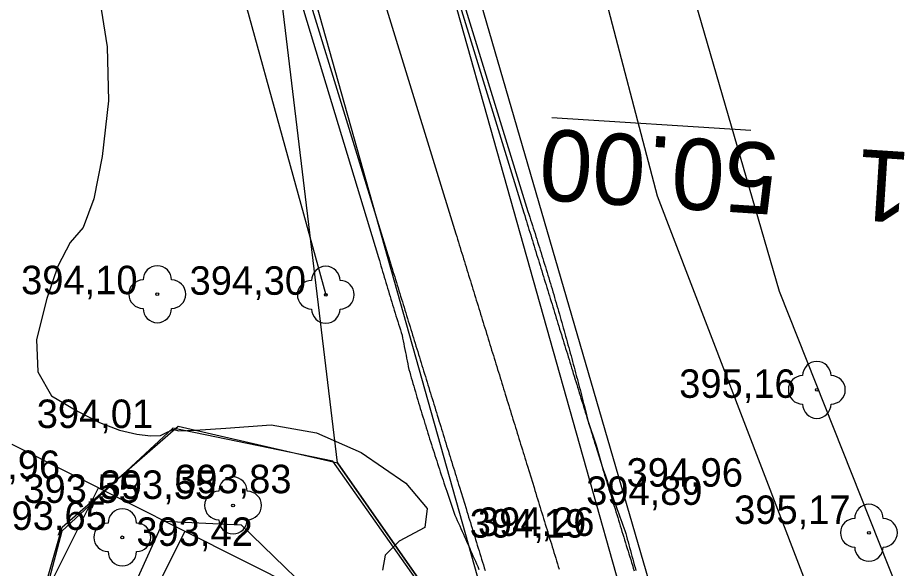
# Model space of a CAD drawing. Extents: x -574342 to -507939, y -1144044 to -1123894.
# Drawn here: x -508498.24 to -508467.17, y -1143116.72 to -1143097.38 of the extents above; entities that cross this region are included whole.
import ezdxf

# ---------------------------------------------------------------- set-up
doc = ezdxf.new("R2010")
doc.units = 0
for name, color, linetype in [('01_PARCELY_NAVRH_PC', 7, 'Continuous'), ('01_PARCELY_NAVRH_VHO', 7, 'Continuous'), ('01_PARCELY_NAVRH_ŽP', 7, 'Continuous'), ('1000', 7, 'Continuous'), ('19', 7, 'Continuous'), ('21', 7, 'Continuous'), ('37', 7, 'Continuous'), ('51', 7, 'Continuous'), ('54', 7, 'Continuous'), ('55', 7, 'Continuous'), ('6', 7, 'Continuous'), ('60', 7, 'Continuous'), ('Level 255', 7, 'Continuous'), ('SO 101_popis oblouku', 7, 'Continuous'), ('VRST VEDL', 7, 'Continuous')]:
    doc.layers.add(name, color=color, linetype=linetype)

msp = doc.modelspace()

# ---------------------------------------------------------------- linework, layer by layer
at = {"layer": '01_PARCELY_NAVRH_PC'}
msp.add_lwpolyline([(-508499.26, -1143041.98), (-508491.15, -1143065.29), (-508474.05, -1143124.14), (-508479.46, -1143126.74), (-508483.82, -1143117.57), (-508487.01, -1143113.01), (-508489.36, -1143093.44), (-508498.08, -1143065.7), (-508506.03, -1143042.25)], close=True, dxfattribs=at)
at = {"layer": '01_PARCELY_NAVRH_VHO'}
msp.add_lwpolyline([(-508498.01, -1143119.91), (-508496.68, -1143115.27), (-508492.61, -1143111.73), (-508487.01, -1143113.01), (-508483.82, -1143117.57)], dxfattribs=at)
at = {"layer": '01_PARCELY_NAVRH_ŽP'}
msp.add_lwpolyline([(-508540.355, -1142847.7), (-508503.94, -1143018.7), (-508499.26, -1143041.98), (-508491.15, -1143065.29), (-508474.05, -1143124.14), (-508467.92, -1143139.18), (-508459.97, -1143152.33), (-508456.09, -1143158.71), (-508451.57, -1143168.14), (-508437.66, -1143207.58), (-508425.52, -1143241.92), (-508422.7, -1143249.88), (-508420.04, -1143252.1), (-508417.38, -1143252.95), (-508415.56, -1143252.78), (-508448.24, -1143160.16), (-508453.75, -1143145.01), (-508465.11, -1143123.03), (-508471.48, -1143106.99), (-508484.55, -1143061.98), (-508495.62, -1143031.06), (-508523.23, -1142904.28), (-508534.61, -1142847.7)], dxfattribs=at)
for points in [[(-508415.56, -1143252.78), (-508448.24, -1143160.16), (-508453.75, -1143145.01), (-508465.11, -1143123.03), (-508471.48, -1143106.99), (-508484.55, -1143061.98), (-508446.15, -1143057.71)], [(-508523.79, -1143164.91), (-508521.99, -1143159.7), (-508510.09, -1143151.01), (-508503.75, -1143144.67), (-508499.11, -1143135.6), (-508498.41, -1143129.24), (-508498.01, -1143119.91), (-508496.68, -1143115.27), (-508492.61, -1143111.73), (-508487.01, -1143113.01), (-508489.36, -1143093.44), (-508492.06, -1143088.51), (-508497.53, -1143088.05), (-508501.63, -1143092.13), (-508501.93, -1143102.81), (-508505.79, -1143121.37), (-508513.07, -1143136.47), (-508529.25, -1143158.67), (-508535.17, -1143170.73), (-508530.07, -1143174.68), (-508525.32, -1143175.64)]]:
    msp.add_lwpolyline(points, close=True, dxfattribs=at)
at = {"layer": '1000'}
for points in [[(-508486.074, -1143086.015), (-508480.463, -1143104.231), (-508480.433, -1143104.329), (-508480.403, -1143104.426), (-508480.373, -1143104.523), (-508480.343, -1143104.62), (-508480.313, -1143104.718), (-508480.283, -1143104.815), (-508480.253, -1143104.912), (-508480.223, -1143105.009), (-508480.193, -1143105.106), (-508480.163, -1143105.204), (-508480.133, -1143105.301), (-508480.103, -1143105.398), (-508480.073, -1143105.495), (-508480.043, -1143105.593), (-508480.013, -1143105.69), (-508479.983, -1143105.787), (-508479.953, -1143105.884), (-508479.924, -1143105.981), (-508479.894, -1143106.079), (-508479.864, -1143106.176), (-508479.834, -1143106.273), (-508479.804, -1143106.37), (-508479.774, -1143106.468), (-508479.744, -1143106.565), (-508479.714, -1143106.662), (-508479.684, -1143106.759), (-508479.654, -1143106.856), (-508479.624, -1143106.954), (-508479.594, -1143107.051), (-508479.564, -1143107.148), (-508479.534, -1143107.245), (-508479.504, -1143107.343), (-508479.474, -1143107.44), (-508479.444, -1143107.537), (-508479.414, -1143107.634), (-508479.384, -1143107.731), (-508479.355, -1143107.829), (-508479.325, -1143107.926), (-508479.295, -1143108.023), (-508479.265, -1143108.12), (-508479.235, -1143108.218), (-508479.205, -1143108.315), (-508479.175, -1143108.412), (-508479.145, -1143108.509), (-508479.115, -1143108.606), (-508479.085, -1143108.704), (-508479.055, -1143108.801), (-508479.025, -1143108.898), (-508478.995, -1143108.995), (-508478.965, -1143109.093), (-508478.935, -1143109.19), (-508478.905, -1143109.287), (-508478.875, -1143109.384), (-508478.845, -1143109.481), (-508478.815, -1143109.579), (-508478.786, -1143109.676), (-508478.756, -1143109.773), (-508478.726, -1143109.87), (-508478.696, -1143109.968), (-508478.669, -1143110.055), (-508478.666, -1143110.065), (-508478.636, -1143110.162), (-508478.606, -1143110.259), (-508478.576, -1143110.357), (-508478.546, -1143110.454), (-508478.516, -1143110.551), (-508478.486, -1143110.648), (-508478.456, -1143110.745), (-508478.426, -1143110.843), (-508478.396, -1143110.94), (-508478.366, -1143111.037), (-508478.336, -1143111.134), (-508478.306, -1143111.232), (-508478.276, -1143111.329), (-508478.246, -1143111.426), (-508478.216, -1143111.523), (-508478.187, -1143111.62), (-508478.157, -1143111.718), (-508478.127, -1143111.815), (-508478.097, -1143111.912), (-508478.067, -1143112.009), (-508478.037, -1143112.107), (-508478.007, -1143112.204), (-508477.977, -1143112.301), (-508477.947, -1143112.398), (-508477.716, -1143113.147), (-508477.686, -1143113.246), (-508477.655, -1143113.345), (-508477.625, -1143113.444), (-508477.594, -1143113.543), (-508477.564, -1143113.642), (-508477.533, -1143113.741), (-508477.503, -1143113.84), (-508477.472, -1143113.939), (-508477.442, -1143114.038), (-508477.411, -1143114.137), (-508477.381, -1143114.236), (-508477.35, -1143114.335), (-508477.32, -1143114.434), (-508477.289, -1143114.533), (-508477.259, -1143114.632), (-508477.228, -1143114.731), (-508477.198, -1143114.83), (-508477.167, -1143114.929), (-508477.137, -1143115.028), (-508477.106, -1143115.127), (-508477.076, -1143115.226), (-508477.046, -1143115.325), (-508477.015, -1143115.424), (-508476.985, -1143115.523), (-508476.954, -1143115.622), (-508476.924, -1143115.721), (-508476.893, -1143115.82), (-508476.863, -1143115.918), (-508476.832, -1143116.017), (-508476.802, -1143116.116), (-508476.771, -1143116.215), (-508476.741, -1143116.314), (-508476.71, -1143116.413), (-508476.68, -1143116.512), (-508476.649, -1143116.611), (-508476.619, -1143116.71), (-508476.588, -1143116.809)], [(-508485.925, -1143085.969), (-508480.32, -1143104.188), (-508480.289, -1143104.284), (-508480.257, -1143104.381), (-508480.226, -1143104.478), (-508480.195, -1143104.575), (-508480.164, -1143104.671), (-508480.132, -1143104.768), (-508480.101, -1143104.865), (-508480.071, -1143104.962), (-508480.04, -1143105.059), (-508480.009, -1143105.156), (-508479.978, -1143105.253), (-508479.948, -1143105.35), (-508479.918, -1143105.447), (-508479.887, -1143105.544), (-508479.857, -1143105.642), (-508479.827, -1143105.739), (-508479.797, -1143105.836), (-508479.767, -1143105.933), (-508479.737, -1143106.03), (-508479.707, -1143106.128), (-508479.678, -1143106.225), (-508479.648, -1143106.322), (-508479.619, -1143106.42), (-508479.589, -1143106.517), (-508479.56, -1143106.615), (-508479.531, -1143106.712), (-508479.502, -1143106.809), (-508479.473, -1143106.907), (-508479.444, -1143107.005), (-508479.415, -1143107.102), (-508479.386, -1143107.2), (-508479.357, -1143107.297), (-508479.329, -1143107.395), (-508479.3, -1143107.493), (-508479.272, -1143107.59), (-508479.244, -1143107.688), (-508479.216, -1143107.786), (-508479.188, -1143107.884), (-508479.16, -1143107.982), (-508479.132, -1143108.079), (-508479.104, -1143108.177), (-508479.076, -1143108.275), (-508479.049, -1143108.373), (-508479.021, -1143108.471), (-508478.994, -1143108.569), (-508478.966, -1143108.667), (-508478.939, -1143108.765), (-508478.912, -1143108.863), (-508478.885, -1143108.961), (-508478.858, -1143109.06), (-508478.831, -1143109.158), (-508478.804, -1143109.256), (-508478.778, -1143109.354), (-508478.751, -1143109.452), (-508478.725, -1143109.551), (-508478.698, -1143109.649), (-508478.672, -1143109.747), (-508478.646, -1143109.846), (-508478.62, -1143109.944), (-508478.596, -1143110.033), (-508478.593, -1143110.043), (-508478.568, -1143110.141), (-508478.542, -1143110.24), (-508478.516, -1143110.338), (-508478.49, -1143110.437), (-508478.465, -1143110.535), (-508478.439, -1143110.634), (-508478.414, -1143110.732), (-508478.389, -1143110.831), (-508478.363, -1143110.93), (-508478.338, -1143111.029), (-508478.313, -1143111.127), (-508478.289, -1143111.226), (-508478.264, -1143111.325), (-508478.239, -1143111.424), (-508478.214, -1143111.523), (-508477.926, -1143112.392), (-508477.71, -1143113.145), (-508477.676, -1143113.243), (-508477.643, -1143113.341), (-508477.609, -1143113.439), (-508477.575, -1143113.537), (-508477.541, -1143113.635), (-508477.507, -1143113.733), (-508477.473, -1143113.831), (-508477.439, -1143113.929), (-508477.405, -1143114.027), (-508477.37, -1143114.124), (-508477.336, -1143114.222), (-508477.301, -1143114.32), (-508477.267, -1143114.418), (-508477.232, -1143114.515), (-508477.197, -1143114.613), (-508477.162, -1143114.71), (-508477.127, -1143114.808), (-508477.092, -1143114.906), (-508477.057, -1143115.003), (-508477.022, -1143115.101), (-508476.986, -1143115.198), (-508476.951, -1143115.296), (-508476.915, -1143115.393), (-508476.882, -1143115.491), (-508476.856, -1143115.591), (-508476.829, -1143115.691), (-508476.802, -1143115.792), (-508476.775, -1143115.892), (-508476.749, -1143115.992), (-508476.722, -1143116.092), (-508476.694, -1143116.192), (-508476.667, -1143116.292), (-508476.64, -1143116.392), (-508476.613, -1143116.492), (-508476.585, -1143116.592), (-508476.558, -1143116.691), (-508476.53, -1143116.791)], [(-508489.541, -1143091.744), (-508485.241, -1143105.703), (-508485.211, -1143105.801), (-508485.181, -1143105.898), (-508485.151, -1143105.995), (-508485.121, -1143106.092), (-508485.091, -1143106.189), (-508485.061, -1143106.287), (-508485.031, -1143106.384), (-508485.001, -1143106.481), (-508484.972, -1143106.578), (-508484.942, -1143106.676), (-508484.912, -1143106.773), (-508484.882, -1143106.87), (-508484.852, -1143106.967), (-508484.822, -1143107.064), (-508484.792, -1143107.162), (-508484.762, -1143107.259), (-508484.732, -1143107.356), (-508484.702, -1143107.453), (-508484.672, -1143107.551), (-508484.642, -1143107.648), (-508484.612, -1143107.745), (-508484.582, -1143107.842), (-508484.552, -1143107.939), (-508484.522, -1143108.037), (-508484.492, -1143108.134), (-508484.462, -1143108.231), (-508484.432, -1143108.328), (-508484.403, -1143108.426), (-508484.373, -1143108.523), (-508484.343, -1143108.62), (-508484.313, -1143108.717), (-508484.283, -1143108.814), (-508484.253, -1143108.912), (-508484.223, -1143109.009), (-508484.193, -1143109.106), (-508484.163, -1143109.203), (-508484.133, -1143109.301), (-508484.103, -1143109.398), (-508484.073, -1143109.495), (-508484.043, -1143109.592), (-508484.013, -1143109.689), (-508483.983, -1143109.787), (-508483.953, -1143109.884), (-508483.923, -1143109.981), (-508483.893, -1143110.078), (-508483.863, -1143110.176), (-508483.833, -1143110.273), (-508483.804, -1143110.37), (-508483.774, -1143110.467), (-508483.744, -1143110.565), (-508483.714, -1143110.662), (-508483.684, -1143110.759), (-508483.654, -1143110.856), (-508483.624, -1143110.953), (-508483.594, -1143111.051), (-508483.564, -1143111.148), (-508483.534, -1143111.245), (-508483.504, -1143111.342), (-508483.474, -1143111.44), (-508483.447, -1143111.527), (-508483.444, -1143111.537), (-508483.414, -1143111.634), (-508483.384, -1143111.731), (-508483.354, -1143111.828), (-508483.324, -1143111.926), (-508483.294, -1143112.023), (-508483.264, -1143112.12), (-508483.235, -1143112.217), (-508483.205, -1143112.315), (-508483.175, -1143112.412), (-508483.145, -1143112.509), (-508483.115, -1143112.606), (-508483.085, -1143112.703), (-508483.055, -1143112.801), (-508483.025, -1143112.898), (-508482.995, -1143112.995), (-508482.965, -1143113.092), (-508482.935, -1143113.19), (-508482.905, -1143113.287), (-508482.875, -1143113.384), (-508482.845, -1143113.481), (-508482.815, -1143113.578), (-508482.785, -1143113.676), (-508482.755, -1143113.773), (-508482.725, -1143113.87), (-508482.495, -1143114.619), (-508482.464, -1143114.718), (-508482.434, -1143114.817), (-508482.403, -1143114.916), (-508482.373, -1143115.015), (-508482.342, -1143115.114), (-508482.312, -1143115.213), (-508482.281, -1143115.312), (-508482.251, -1143115.411), (-508482.22, -1143115.51), (-508482.19, -1143115.609), (-508482.159, -1143115.708), (-508482.129, -1143115.807), (-508482.098, -1143115.906), (-508482.068, -1143116.005), (-508482.037, -1143116.104), (-508482.007, -1143116.203), (-508481.976, -1143116.302), (-508481.946, -1143116.401), (-508481.915, -1143116.5), (-508481.885, -1143116.599), (-508481.854, -1143116.698), (-508481.824, -1143116.797)], [(-508489.501, -1143092.82), (-508485.568, -1143105.804), (-508485.54, -1143105.902), (-508485.512, -1143106), (-508485.483, -1143106.097), (-508485.455, -1143106.195), (-508485.426, -1143106.293), (-508485.398, -1143106.39), (-508485.369, -1143106.488), (-508485.34, -1143106.585), (-508485.311, -1143106.683), (-508485.282, -1143106.78), (-508485.253, -1143106.878), (-508485.223, -1143106.975), (-508485.194, -1143107.073), (-508485.164, -1143107.17), (-508485.135, -1143107.267), (-508485.105, -1143107.365), (-508485.075, -1143107.462), (-508485.045, -1143107.559), (-508485.015, -1143107.656), (-508484.985, -1143107.753), (-508484.955, -1143107.851), (-508484.924, -1143107.948), (-508484.894, -1143108.045), (-508484.863, -1143108.142), (-508484.833, -1143108.239), (-508484.802, -1143108.336), (-508484.771, -1143108.433), (-508484.74, -1143108.53), (-508484.721, -1143108.63), (-508484.701, -1143108.731), (-508484.682, -1143108.831), (-508484.662, -1143108.931), (-508484.642, -1143109.032), (-508484.623, -1143109.132), (-508484.603, -1143109.232), (-508484.583, -1143109.333), (-508484.562, -1143109.433), (-508484.544, -1143109.534), (-508484.528, -1143109.635), (-508484.5, -1143109.733), (-508484.473, -1143109.831), (-508484.445, -1143109.929), (-508484.416, -1143110.027), (-508484.388, -1143110.124), (-508484.36, -1143110.222), (-508484.332, -1143110.32), (-508484.303, -1143110.417), (-508484.274, -1143110.515), (-508484.246, -1143110.613), (-508484.217, -1143110.71), (-508484.188, -1143110.808), (-508484.159, -1143110.905), (-508484.13, -1143111.003), (-508484.1, -1143111.1), (-508484.071, -1143111.198), (-508484.042, -1143111.295), (-508484.012, -1143111.392), (-508483.982, -1143111.49), (-508483.952, -1143111.587), (-508483.925, -1143111.675), (-508483.923, -1143111.684), (-508483.893, -1143111.781), (-508483.862, -1143111.879), (-508483.832, -1143111.976), (-508483.802, -1143112.073), (-508483.772, -1143112.17), (-508483.741, -1143112.267), (-508483.71, -1143112.364), (-508483.68, -1143112.461), (-508483.649, -1143112.558), (-508483.618, -1143112.655), (-508483.587, -1143112.752), (-508483.556, -1143112.848), (-508483.524, -1143112.945), (-508483.493, -1143113.042), (-508483.462, -1143113.139), (-508483.43, -1143113.236), (-508483.398, -1143113.332), (-508483.366, -1143113.429), (-508483.335, -1143113.526), (-508483.303, -1143113.622), (-508483.27, -1143113.719), (-508483.238, -1143113.815), (-508483.206, -1143113.912), (-508483.173, -1143114.008), (-508482.923, -1143114.751), (-508482.889, -1143114.849), (-508482.846, -1143114.944), (-508482.803, -1143115.039), (-508482.759, -1143115.134), (-508482.716, -1143115.229), (-508482.674, -1143115.325), (-508482.631, -1143115.42), (-508482.588, -1143115.515), (-508482.545, -1143115.61), (-508482.503, -1143115.705), (-508482.461, -1143115.801), (-508482.418, -1143115.896), (-508482.376, -1143115.991), (-508482.334, -1143116.087), (-508482.292, -1143116.182), (-508482.25, -1143116.278), (-508482.208, -1143116.373), (-508482.167, -1143116.469), (-508482.125, -1143116.564), (-508482.084, -1143116.66), (-508482.042, -1143116.756)]]:
    msp.add_lwpolyline(points, dxfattribs=at)
at = {"layer": '21'}
msp.add_lwpolyline([(-508488.463, -1143086.751), (-508482.852, -1143104.967), (-508482.822, -1143105.065), (-508482.792, -1143105.162), (-508482.762, -1143105.259), (-508482.732, -1143105.356), (-508482.702, -1143105.453), (-508482.672, -1143105.551), (-508482.642, -1143105.648), (-508482.612, -1143105.745), (-508482.582, -1143105.842), (-508482.552, -1143105.94), (-508482.522, -1143106.037), (-508482.492, -1143106.134), (-508482.463, -1143106.231), (-508482.433, -1143106.328), (-508482.403, -1143106.426), (-508482.373, -1143106.523), (-508482.343, -1143106.62), (-508482.313, -1143106.717), (-508482.283, -1143106.815), (-508482.253, -1143106.912), (-508482.223, -1143107.009), (-508482.193, -1143107.106), (-508482.163, -1143107.204), (-508482.133, -1143107.301), (-508482.103, -1143107.398), (-508482.073, -1143107.495), (-508482.043, -1143107.592), (-508482.013, -1143107.69), (-508481.983, -1143107.787), (-508481.953, -1143107.884), (-508481.923, -1143107.981), (-508481.893, -1143108.079), (-508481.864, -1143108.176), (-508481.834, -1143108.273), (-508481.804, -1143108.37), (-508481.774, -1143108.467), (-508481.744, -1143108.565), (-508481.714, -1143108.662), (-508481.684, -1143108.759), (-508481.654, -1143108.856), (-508481.624, -1143108.954), (-508481.594, -1143109.051), (-508481.564, -1143109.148), (-508481.534, -1143109.245), (-508481.504, -1143109.342), (-508481.474, -1143109.44), (-508481.444, -1143109.537), (-508481.414, -1143109.634), (-508481.384, -1143109.731), (-508481.354, -1143109.829), (-508481.324, -1143109.926), (-508481.295, -1143110.023), (-508481.265, -1143110.12), (-508481.235, -1143110.217), (-508481.205, -1143110.315), (-508481.175, -1143110.412), (-508481.145, -1143110.509), (-508481.115, -1143110.606), (-508481.085, -1143110.704), (-508481.058, -1143110.791), (-508481.055, -1143110.801), (-508481.025, -1143110.898), (-508480.995, -1143110.995), (-508480.965, -1143111.092), (-508480.935, -1143111.19), (-508480.905, -1143111.287), (-508480.875, -1143111.384), (-508480.845, -1143111.481), (-508480.815, -1143111.579), (-508480.785, -1143111.676), (-508480.755, -1143111.773), (-508480.726, -1143111.87), (-508480.696, -1143111.967), (-508480.666, -1143112.065), (-508480.636, -1143112.162), (-508480.606, -1143112.259), (-508480.576, -1143112.356), (-508480.546, -1143112.454), (-508480.516, -1143112.551), (-508480.486, -1143112.648), (-508480.456, -1143112.745), (-508480.426, -1143112.842), (-508480.396, -1143112.94), (-508480.366, -1143113.037), (-508480.336, -1143113.134), (-508480.105, -1143113.883), (-508480.075, -1143113.982), (-508480.044, -1143114.081), (-508480.014, -1143114.18), (-508479.983, -1143114.279), (-508479.953, -1143114.378), (-508479.922, -1143114.477), (-508479.892, -1143114.576), (-508479.862, -1143114.675), (-508479.831, -1143114.774), (-508479.801, -1143114.873), (-508479.77, -1143114.972), (-508479.74, -1143115.071), (-508479.709, -1143115.17), (-508479.679, -1143115.269), (-508479.648, -1143115.368), (-508479.618, -1143115.467), (-508479.587, -1143115.566), (-508479.557, -1143115.665), (-508479.526, -1143115.764), (-508479.496, -1143115.863), (-508479.465, -1143115.962), (-508479.435, -1143116.061), (-508479.404, -1143116.16), (-508479.374, -1143116.259), (-508479.343, -1143116.358), (-508479.313, -1143116.457), (-508479.282, -1143116.555), (-508479.252, -1143116.654), (-508479.221, -1143116.753)], dxfattribs=at)
at = {"layer": '37'}
msp.add_lwpolyline([(-508476.03, -1143123.74), (-508475.36, -1143123.53), (-508484.42, -1143091.34), (-508494.04, -1143058.06), (-508495.34, -1143058.46), (-508498.68, -1143059.63), (-508488.94, -1143092.68), (-508479.81, -1143125.14), (-508478.76, -1143124.67)], dxfattribs=at)
msp.add_lwpolyline([(-508476.03, -1143123.74), (-508475.36, -1143123.53), (-508484.42, -1143091.34), (-508494.04, -1143058.06), (-508495.34, -1143058.46), (-508498.68, -1143059.63), (-508488.94, -1143092.68), (-508479.81, -1143125.14), (-508478.76, -1143124.67)], dxfattribs=at)
at = {"layer": '51'}
msp.add_lwpolyline([(-508520.2, -1143160.98), (-508507.66, -1143152.38), (-508503.68, -1143148.5), (-508498.94, -1143141.93), (-508496.26, -1143135.35), (-508495.95, -1143129.08), (-508495.44, -1143120.19), (-508493.12, -1143115.06), (-508490.39, -1143115.19), (-508486.94, -1143118.54), (-508484.73, -1143123.98), (-508484.03, -1143128.35), (-508482.47, -1143135.96), (-508481.24, -1143143.89), (-508483.67, -1143147.96), (-508487.25, -1143151.23), (-508497.6, -1143155.8), (-508504.12, -1143160.81), (-508512.14, -1143168.95), (-508515.5, -1143169.45), (-508518.57, -1143168.12), (-508521.82, -1143163.95)], close=True, dxfattribs=at)
msp.add_lwpolyline([(-508520.2, -1143160.98), (-508507.66, -1143152.38), (-508503.68, -1143148.5), (-508498.94, -1143141.93), (-508496.26, -1143135.35), (-508495.95, -1143129.08), (-508495.44, -1143120.19), (-508493.12, -1143115.06), (-508490.39, -1143115.19), (-508486.94, -1143118.54), (-508484.73, -1143123.98), (-508484.03, -1143128.35), (-508482.47, -1143135.96), (-508481.24, -1143143.89), (-508483.67, -1143147.96), (-508487.25, -1143151.23), (-508497.6, -1143155.8), (-508504.12, -1143160.81), (-508512.14, -1143168.95), (-508515.5, -1143169.45), (-508518.57, -1143168.12), (-508521.82, -1143163.95)], close=True, dxfattribs=at)
at = {"layer": '54'}
for centre in [(-508493.34, -1143107.09), (-508487.42, -1143107.11), (-508470.17, -1143110.45), (-508490.68, -1143114.51), (-508494.57, -1143115.63), (-508468.34, -1143115.47)]:
    msp.add_circle(centre, 0.05, dxfattribs=at)
for centre, start, end in [((-508493.34, -1143106.59), 0, 180), ((-508487.42, -1143106.61), 0, 180), ((-508493.84, -1143107.09), 90, 270), ((-508492.84, -1143107.09), 270, 90), ((-508487.92, -1143107.11), 90, 270), ((-508486.92, -1143107.11), 270, 90), ((-508493.34, -1143107.59), 180, 0), ((-508487.42, -1143107.61), 180, 0), ((-508470.17, -1143109.95), 0, 180), ((-508470.67, -1143110.45), 90, 270), ((-508469.67, -1143110.45), 270, 90), ((-508470.17, -1143110.95), 180, 0), ((-508490.68, -1143114.01), 0, 180), ((-508491.18, -1143114.51), 90, 270), ((-508490.18, -1143114.51), 270, 90), ((-508494.57, -1143115.13), 0, 180), ((-508468.34, -1143114.97), 0, 180), ((-508495.07, -1143115.63), 90, 270), ((-508494.07, -1143115.63), 270, 90), ((-508490.68, -1143115.01), 180, 0), ((-508468.84, -1143115.47), 90, 270), ((-508467.84, -1143115.47), 270, 90), ((-508494.57, -1143116.13), 180, 0), ((-508468.34, -1143115.97), 180, 0)]:
    msp.add_arc(centre, 0.5, start, end, dxfattribs=at)
at = {"layer": '55'}
msp.add_line((-508492.39, -1143089.07), (-508487.42, -1143107.11), dxfattribs=at)
msp.add_line((-508492.39, -1143089.07), (-508487.42, -1143107.11), dxfattribs=at)
msp.add_lwpolyline([(-508486.89, -1143065.21), (-508480.57, -1143088.37), (-508477.81, -1143095.89), (-508475.78, -1143103.63), (-508468.39, -1143122.87), (-508456.91, -1143145.22), (-508451.68, -1143159.54), (-508438.58, -1143205.02)], dxfattribs=at)
msp.add_lwpolyline([(-508486.89, -1143065.21), (-508480.57, -1143088.37), (-508477.81, -1143095.89), (-508475.78, -1143103.63), (-508468.39, -1143122.87), (-508456.91, -1143145.22), (-508451.68, -1143159.54), (-508438.58, -1143205.02)], dxfattribs=at)
at = {"layer": '6'}
msp.add_lwpolyline([(-508472.492, -1143101.345), (-508479.477, -1143100.896)], dxfattribs=at)
at = {"layer": '60'}
msp.add_lwpolyline([(-508483.98, -1143117.49), (-508487.17, -1143112.95), (-508492.79, -1143111.79), (-508496.69, -1143115.41), (-508498.11, -1143120.78)], dxfattribs=at)
msp.add_lwpolyline([(-508483.98, -1143117.49), (-508487.17, -1143112.95), (-508492.79, -1143111.79), (-508496.69, -1143115.41), (-508498.11, -1143120.78)], dxfattribs=at)
at = {"layer": 'SO 101_popis oblouku'}
for p, q in [((-508498.446, -1143112.358), (-508483.255, -1143119.988)), ((-508495.408, -1143113.884), (-508505.581, -1143134.139)), ((-508492.37, -1143115.41), (-508502.543, -1143135.665))]:
    msp.add_line(p, q, dxfattribs=at)
at = {"layer": 'VRST VEDL'}
msp.add_lwpolyline([(-508495.39, -1143096.554), (-508495.099, -1143098.401), (-508495.06, -1143100.303), (-508495.274, -1143102.257), (-508495.57, -1143103.737), (-508495.947, -1143104.742), (-508496.405, -1143105.272), (-508496.832, -1143106.105), (-508497.227, -1143107.242), (-508497.59, -1143108.683), (-508497.536, -1143109.821), (-508497.063, -1143110.657), (-508496.173, -1143111.192), (-508495.375, -1143111.595), (-508494.67, -1143111.866), (-508494.057, -1143112.007), (-508493.577, -1143112.068), (-508493.229, -1143112.048), (-508493.015, -1143111.947), (-508492.865, -1143111.88), (-508492.781, -1143111.846), (-508492.761, -1143111.845), (-508492.724, -1143111.853), (-508492.668, -1143111.868), (-508492.594, -1143111.893), (-508492.014, -1143111.869), (-508490.929, -1143111.798), (-508489.337, -1143111.678), (-508487.753, -1143111.961), (-508486.178, -1143112.645), (-508484.61, -1143113.731), (-508483.865, -1143114.612), (-508483.941, -1143115.288), (-508484.84, -1143115.76), (-508485.337, -1143116.26), (-508485.43, -1143116.787)], dxfattribs=at)

# ---------------------------------------------------------------- texts
at = {"layer": '19'}
msp.add_text('P1   50.00', height=2.5, rotation=176.3262, dxfattribs=at).set_placement((-508464.613, -1143102.251))
at = {"layer": 'Level 255'}
for s, p in [('394,10', (-508498.125, -1143107.09)), ('394,30', (-508492.205, -1143107.11)), ('395,16', (-508475.005, -1143110.73)), ('394,01', (-508497.575, -1143111.79)), ('393,96', (-508500.845, -1143113.58)), ('393,83', (-508492.715, -1143114.08)), ('394,96', (-508476.855, -1143113.85)), ('393,55', (-508498.045, -1143114.42)), ('393,55', (-508495.365, -1143114.28)), ('394,89', (-508478.275, -1143114.49)), ('395,17', (-508473.075, -1143115.16)), ('393,65', (-508499.205, -1143115.37)), ('394,19', (-508482.365, -1143115.64)), ('394,26', (-508482.075, -1143115.58)), ('393,42', (-508494.075, -1143115.93))]:
    msp.add_text(s, height=1, dxfattribs=at).set_placement(p)

doc.saveas('drawing.dxf')
